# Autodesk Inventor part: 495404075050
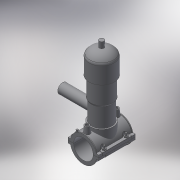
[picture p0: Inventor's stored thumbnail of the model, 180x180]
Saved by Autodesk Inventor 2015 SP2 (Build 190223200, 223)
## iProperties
Created: 2017-07
Part Number: 495404075050
Material: Generic
Description: PLASSON TAPPING VALVE 75-50
Document SubType Name: Modeling
Designer: KIM
Density: 1 g/cm^3
Appearance: Default
Author: KIM
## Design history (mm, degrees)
derived "495404-4954S4.ipt"
feature "Solid1::495404-4954S4.ipt"
feature "Solid2::495404-4954S4.ipt"
tag "TaggingFeature1"
body "Solid1"
body "Solid2"
other parameters: "d_" = 75, "B_" = 117, "H_" = 152, "L_" = 118, "d_t" = 6, "H_1" = 51, "H_2" = 244, "d148" = 1.125, "d160" = 1.125, "d169" = 3, "d192" = 6.8, "d0" = 75, "d2" = 117, "d3" = 18.75, "d4" = 118, "d5" = 0, "d6" = 0.1, "d8" = 0, "d19" = 6, "d20" = 6, "d21" = 70.8, "d23" = 0, "d24" = 35.4, "d26" = 0, "d27" = 3, "d28" = 3, "d29" = 3, "d30" = 25, "d31" = 6, "d32" = 0, "d33" = 0, "d34" = 0.6, "d40" = 50.7, "d47" = 99.75, "d70" = 15, "d72" = 0, "d73" = 6, "d75" = 5, "d76" = 0, "d77" = 3.75, "d78" = 67.5, "d79" = 15, "d80" = 47.2, "d82" = 5 deg, "d84" = 4, "d85" = 14, "d86" = 0, "d87" = 3, "d88" = 0, "d89" = 1, "d90" = 1, "d91" = 94.4, "d92" = 0, "d93" = 0.5, "d94" = 39.47368, "d96" = 100.425, "d97" = 2.36, "d98" = 0, "d120" = 140 deg, "d121" = 24.228, "d122" = 20 deg, "d123" = 195, "d124" = 58.5, "d126" = 0, "d143" = 77.25, "d145" = 17.30769, "d149" = 1.125, "d150" = 19.03846, "d153" = 118, "d154" = 0, "d156" = 48.75, "d157" = 160 deg, "d159" = 4.5, "d161" = 1.125, "d162" = 70.8, "d163" = 0, "d164" = 37.5, "d167" = 7.5, "d168" = 47.56098, "d170" = 3, "d172" = 0, "d173" = 1, "d175" = 37.5, "d176" = 20 deg, "d177" = 5.25, "d178" = 22.5, "d180" = 0, "d183" = 9, "d184" = 4.2, "d185" = 38.35, "d186" = 38.35, "d187" = 48.75, "d188" = 6.75, "d189" = 5.25, "d190" = 0, "d191" = 73.125, "d193" = 6.8, "d194" = 2.95, "d195" = 90 deg, "d197" = 0, "d199" = 0, "d205" = 14.64, "d206" = 81.33333, "d207" = 244, "d208" = 224.48, "d209" = 207.4, "d210" = 200.08, "d211" = 146.4, "d212" = 85.4, "d213" = 65.88, "d214" = 73.2, "d216" = 19.52, "d217" = 70.76, "d218" = 80.52, "d220" = 75, "d222" = 0, "d223" = 97.5, "d224" = 152, "d225" = 51, "d229" = 152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
